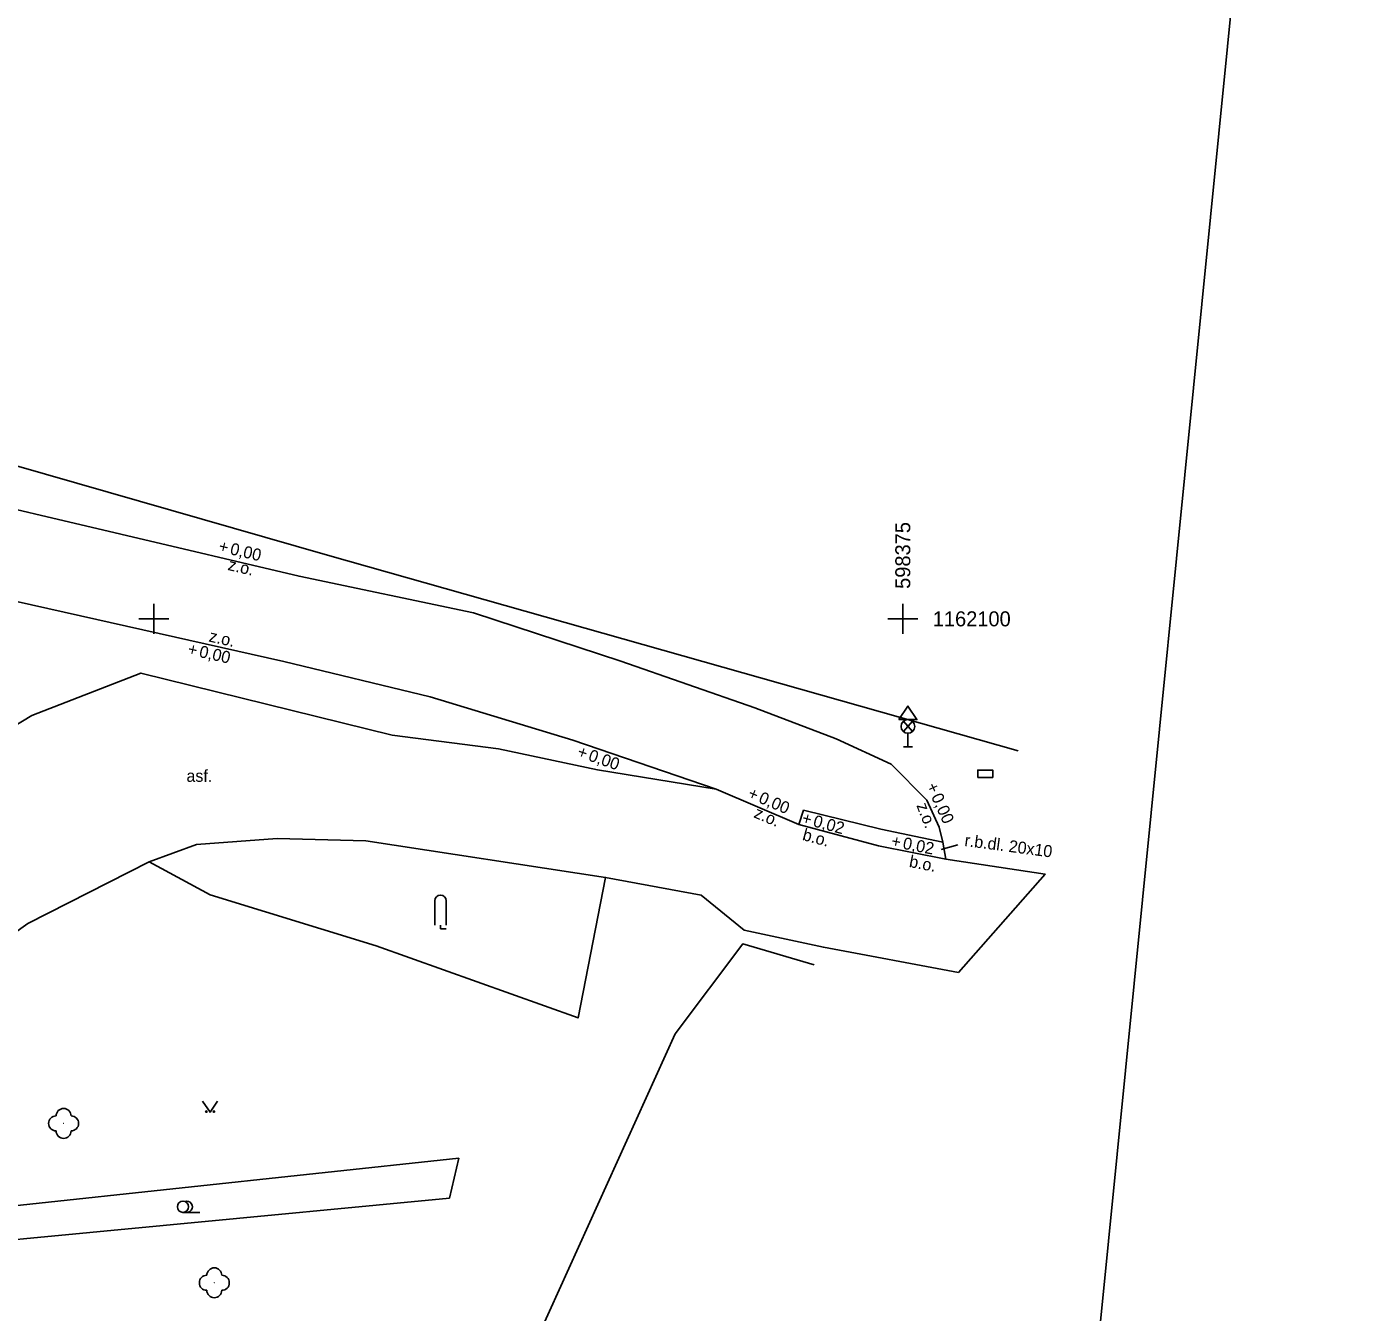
# Model space of a CAD drawing. Extents: x -598693 to -598360, y -1162453 to -1162007.
# Drawn here: x -598404.24 to -598359.63, y -1162123.14 to -1162080.24 of the extents above; entities that cross this region are included whole.
import ezdxf

# ---------------------------------------------------------------- set-up
doc = ezdxf.new("R2010")
doc.units = 0
for name, color, linetype in [('Vrstva 10', 7, 'Continuous'), ('Vrstva 11', 7, 'Continuous'), ('Vrstva 14', 7, 'Continuous'), ('Vrstva 2', 7, 'Continuous'), ('Vrstva 22', 7, 'Continuous'), ('Vrstva 29', 7, 'Continuous'), ('Vrstva 44', 7, 'Continuous'), ('Vrstva 49', 7, 'Continuous'), ('Vrstva 50', 7, 'Continuous'), ('Vrstva 62', 7, 'Continuous'), ('Vrstva 63', 7, 'Continuous'), ('Vrstva 7', 7, 'Continuous')]:
    doc.layers.add(name, color=color, linetype=linetype)

msp = doc.modelspace()

# ---------------------------------------------------------------- linework, layer by layer
at = {"layer": 'Vrstva 10'}
msp.add_lwpolyline([(-598377.96, -1162111.55), (-598380.34, -1162110.85), (-598382.6, -1162113.85), (-598388.4, -1162126.67), (-598389.97, -1162143.7), (-598389.93, -1162150.91), (-598398.41, -1162184.97), (-598409.68, -1162207.21), (-598446.29, -1162278.33)], dxfattribs=at)
at = {"layer": 'Vrstva 11'}
for points in [[(-598390.13, -1162119.34), (-598389.82, -1162118), (-598408.92, -1162120.05), (-598409.26, -1162121.16)], [(-598409.26, -1162121.16), (-598390.13, -1162119.34)]]:
    msp.add_lwpolyline(points, dxfattribs=at)
at = {"layer": 'Vrstva 14'}
for p, q in [((-598390.618, -1162110.22), (-598390.618, -1162109.408)), ((-598390.242, -1162110.22), (-598390.242, -1162109.408)), ((-598399.026, -1162119.81), (-598398.464, -1162119.81))]:
    msp.add_line(p, q, dxfattribs=at)
for points in [[(-598390.43, -1162110.22), (-598390.43, -1162110.345), (-598390.242, -1162110.345)], [(-598398.37, -1162116.095), (-598398.12, -1162116.47), (-598397.87, -1162116.095)]]:
    msp.add_lwpolyline(points, dxfattribs=at)
for centre, radius in [((-598398.245, -1162116.445), 0.025), ((-598397.995, -1162116.445), 0.025), ((-598403.01, -1162116.84), 0.00025), ((-598399.026, -1162119.622), 0.188), ((-598397.98, -1162122.16), 0.00025)]:
    msp.add_circle(centre, radius, dxfattribs=at)
for centre, radius, start, end in [((-598390.43, -1162109.407), 0.188, 0, 180), ((-598403.26, -1162116.84), 0.25, 90, 270), ((-598403.01, -1162116.59), 0.25, 0, 180), ((-598402.76, -1162116.84), 0.25, 270, 90), ((-598403.01, -1162117.09), 0.25, 180, 360), ((-598398.901, -1162119.622), 0.188, 249.4944, 109.0474), ((-598398.23, -1162122.16), 0.25, 90, 270), ((-598397.98, -1162121.91), 0.25, 0, 180), ((-598397.73, -1162122.16), 0.25, 270, 90), ((-598397.98, -1162122.41), 0.25, 180, 360)]:
    msp.add_arc(centre, radius, start, end, dxfattribs=at)
at = {"layer": 'Vrstva 2'}
msp.add_lwpolyline([(-598507.399, -1162020.712), (-598549.031, -1162438.644), (-598401.263, -1162453.364), (-598359.63, -1162035.432)], close=True, dxfattribs=at)
at = {"layer": 'Vrstva 22'}
msp.add_lwpolyline([(-598474.94, -1162078.69), (-598462.32, -1162081.57), (-598450.6, -1162084.22), (-598438.86, -1162086.87), (-598421.29, -1162090.81), (-598412.46, -1162092.76), (-598405.72, -1162094.57), (-598394.2, -1162097.88), (-598371.15, -1162104.4)], dxfattribs=at)
at = {"layer": 'Vrstva 29'}
msp.add_lwpolyline([(-598372.5, -1162105.295), (-598372, -1162105.295), (-598372, -1162105.045), (-598372.5, -1162105.045)], close=True, dxfattribs=at)
at = {"layer": 'Vrstva 44'}
for p, q in [((-598374.68, -1162103.42), (-598374.98, -1162103.764)), ((-598374.98, -1162103.42), (-598374.68, -1162103.764)), ((-598374.83, -1162104.27), (-598374.83, -1162103.82)), ((-598374.98, -1162104.27), (-598374.68, -1162104.27))]:
    msp.add_line(p, q, dxfattribs=at)
msp.add_lwpolyline([(-598375.13, -1162103.364), (-598374.53, -1162103.364), (-598374.83, -1162102.914), (-598375.13, -1162103.364)], dxfattribs=at)
msp.add_circle((-598374.83, -1162103.592), 0.228, dxfattribs=at)
at = {"layer": 'Vrstva 49'}
msp.add_line((-598373.72, -1162107.7), (-598373.16, -1162107.54), dxfattribs=at)
at = {"layer": 'Vrstva 62'}
for p, q in [((-598400, -1162100.5), (-598400, -1162099.5)), ((-598375, -1162100.5), (-598375, -1162099.5)), ((-598400.5, -1162100), (-598399.5, -1162100)), ((-598375.5, -1162100), (-598374.5, -1162100))]:
    msp.add_line(p, q, dxfattribs=at)
at = {"layer": 'Vrstva 63'}
for points in [[(-598407.99, -1162105.6), (-598404.07, -1162103.23), (-598400.43, -1162101.81), (-598392.04, -1162103.88), (-598388.5, -1162104.34), (-598385.19, -1162105.04), (-598381.23, -1162105.69), (-598378.47, -1162106.86), (-598375.81, -1162107.58), (-598373.56, -1162108.02), (-598370.25, -1162108.52), (-598373.14, -1162111.8)], [(-598373.14, -1162111.8), (-598377.65, -1162110.96), (-598380.29, -1162110.39), (-598381.73, -1162109.22), (-598384.92, -1162108.63), (-598392.92, -1162107.41), (-598395.88, -1162107.33), (-598398.58, -1162107.53), (-598400.16, -1162108.11), (-598404.21, -1162110.17), (-598407.95, -1162112.85)]]:
    msp.add_lwpolyline(points, dxfattribs=at)
at = {"layer": 'Vrstva 7'}
for points in [[(-598475.15, -1162080.96), (-598462.81, -1162083.37), (-598450.93, -1162085.93), (-598438.6, -1162088.68), (-598421.45, -1162092.56), (-598407.06, -1162095.77), (-598395.15, -1162098.58), (-598389.33, -1162099.8), (-598384.41, -1162101.41), (-598379.94, -1162102.97), (-598377.22, -1162104), (-598375.39, -1162104.85), (-598374.2, -1162106.05), (-598373.79, -1162106.95), (-598373.66, -1162107.45), (-598373.56, -1162108.02)], [(-598472.69, -1162084.48), (-598463.76, -1162086.22), (-598451.44, -1162088.9), (-598439.43, -1162091.59), (-598422.04, -1162095.48), (-598407.71, -1162098.72), (-598395.66, -1162101.42), (-598390.77, -1162102.6), (-598386.01, -1162104.05), (-598381.23, -1162105.69), (-598378.47, -1162106.86), (-598375.81, -1162107.58), (-598373.56, -1162108.02), (-598370.25, -1162108.52)], [(-598381.23, -1162105.69), (-598385.19, -1162105.04), (-598388.5, -1162104.34), (-598392.04, -1162103.88), (-598400.43, -1162101.81), (-598404.07, -1162103.23), (-598407.99, -1162105.6), (-598411.43, -1162107.96), (-598414.33, -1162110.36), (-598423.25, -1162111.8), (-598438.05, -1162113.94), (-598450.21, -1162115.65), (-598461.04, -1162117.05)], [(-598378.47, -1162106.86), (-598378.31, -1162106.39), (-598375.73, -1162107.02), (-598373.66, -1162107.45)], [(-598373.14, -1162111.8), (-598377.65, -1162110.96), (-598380.29, -1162110.39), (-598381.73, -1162109.22), (-598384.92, -1162108.63), (-598392.92, -1162107.41), (-598395.88, -1162107.33), (-598398.58, -1162107.53), (-598400.16, -1162108.11), (-598404.21, -1162110.17), (-598407.95, -1162112.85), (-598410.38, -1162115.37), (-598412.63, -1162118.72), (-598414.39, -1162122.65), (-598415.24, -1162126.4), (-598415.3, -1162129.3), (-598414.83, -1162130.72)], [(-598384.92, -1162108.63), (-598385.84, -1162113.32), (-598392.58, -1162110.91), (-598398.12, -1162109.21), (-598400.16, -1162108.11)]]:
    msp.add_lwpolyline(points, dxfattribs=at)

# ---------------------------------------------------------------- texts
at = {"layer": 'Vrstva 49'}
for s, rotation, p in [('z.o.', 346.7246, (-598397.552, -1162098.365)), ('z.o.', 347.3705, (-598398.186, -1162100.752)), ('z.o.', 337.0273, (-598380.001, -1162106.616)), ('z.o.', 291.2835, (-598374.551, -1162106.226)), ('b.o.', 344.8543, (-598378.375, -1162107.376)), ('r.b.dl. 20x10', 352.4157, (-598372.956, -1162107.579)), ('b.o.', 348.9351, (-598374.81, -1162108.276))]:
    msp.add_text(s, height=0.4, rotation=rotation, dxfattribs=at).set_placement(p)
msp.add_text('asf.', height=0.4, dxfattribs=at).set_placement((-598398.91, -1162105.44))
at = {"layer": 'Vrstva 50'}
for s, rotation, p in [('+', 346.7246, (-598397.862, -1162097.751)), ('0,00', 346.7246, (-598397.479, -1162097.841)), ('+', 347.3705, (-598398.894, -1162101.184)), ('0,00', 347.3705, (-598398.51, -1162101.27)), ('+', 341.0631, (-598385.895, -1162104.593)), ('0,00', 341.0631, (-598385.523, -1162104.721)), ('+', 337.0273, (-598380.205, -1162105.966)), ('0,00', 337.0273, (-598379.843, -1162106.12)), ('+', 294.4919, (-598374.226, -1162105.574)), ('0,00', 294.4919, (-598374.063, -1162105.932)), ('+', 344.8543, (-598378.398, -1162106.819)), ('0,02', 344.8543, (-598378.018, -1162106.921)), ('+', 348.9351, (-598375.407, -1162107.595)), ('0,02', 348.9351, (-598375.021, -1162107.671))]:
    msp.add_text(s, height=0.4, rotation=rotation, dxfattribs=at).set_placement(p)
at = {"layer": 'Vrstva 62'}
msp.add_text('598375', height=0.5, rotation=90, dxfattribs=at).set_placement((-598374.75, -1162099))
msp.add_text('1162100', height=0.5, dxfattribs=at).set_placement((-598374, -1162100.25))

doc.saveas('drawing.dxf')
